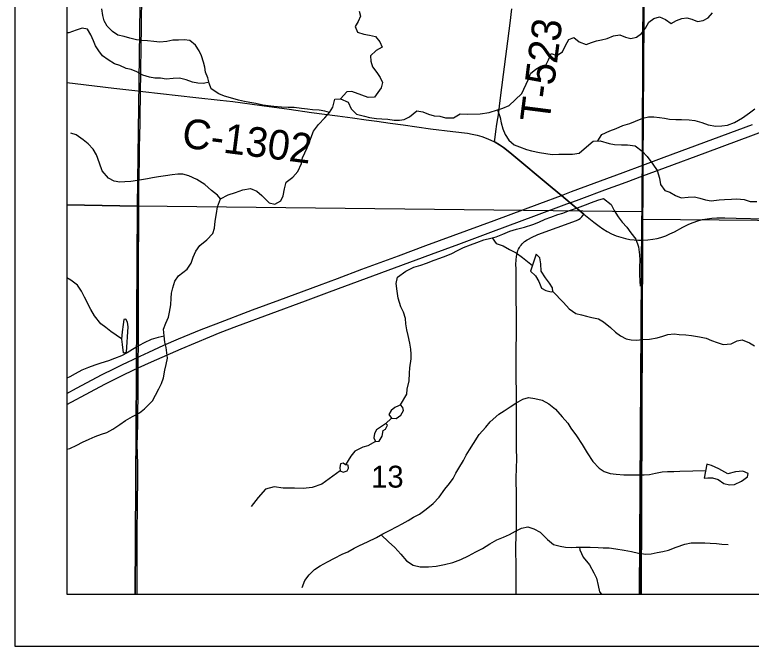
# Model space of a CAD drawing. Extents: x 0 to 34, y 0 to 22.
# Drawn here: x 2 to 3.412, y 14 to 15.21 of the extents above; entities that cross this region are included whole.
import ezdxf

# ---------------------------------------------------------------- set-up
doc = ezdxf.new("R2010")
doc.units = 0
for name, color, linetype in [('Default', 7, 'Continuous'), ('GM_X_County_Road', 7, 'Continuous'), ('GM_X_County_Road_Text', 7, 'Continuous'), ('GM_X_Interstate_Route', 7, 'Continuous'), ('GM_X_Minor_Lake', 7, 'Continuous'), ('GM_X_Minor_River', 7, 'Continuous'), ('GM_X_Section', 7, 'Continuous'), ('GM_X_Section_Text', 7, 'Continuous'), ('GM_X_Township_Road', 7, 'Continuous'), ('GM_X_Township_Road_Text', 7, 'Continuous'), ('SH_Cut_Line', 7, 'Continuous'), ('SH_Data', 7, 'Continuous')]:
    doc.layers.add(name, color=color, linetype=linetype)

msp = doc.modelspace()

# ---------------------------------------------------------------- linework, layer by layer
at = {"layer": 'Default'}
for points in [[(2.1, 15.8527), (2.1, 14.8453), (2.2353, 14.8433), (2.249, 15.8507)], [(2.1, 14.8453), (2.1, 14.1), (2.2309, 14.1), (2.2353, 14.8433)], [(2.2309, 14.1), (3.1977, 14.1), (3.2026, 14.8175), (3.2029, 14.8323), (2.2353, 14.8433)], [(3.1977, 14.1), (4.2188, 14.1), (4.2381, 14.8083), (3.2026, 14.8175)]]:
    msp.add_lwpolyline(points, close=True, dxfattribs=at)
at = {"layer": 'GM_X_County_Road'}
for points in [[(2.1, 15.0799), (2.1161, 15.078), (2.1901, 15.0692), (2.2301, 15.0646), (2.2411, 15.0635)], [(2.2411, 15.0635), (2.2456, 15.063), (2.2795, 15.059), (2.3474, 15.0514), (2.3936, 15.0463), (2.4183, 15.0433), (2.4737, 15.0357), (2.526, 15.0286), (2.5692, 15.0228), (2.6189, 15.0162), (2.6473, 15.0121), (2.6737, 15.0086), (2.694, 15.0057), (2.7198, 15.0023), (2.7446, 14.9986), (2.797, 14.9915), (2.8401, 14.9861), (2.8679, 14.9826), (2.8771, 14.981), (2.8863, 14.979), (2.8953, 14.9764), (2.9041, 14.9733), (2.9128, 14.9697), (2.9199, 14.9662)], [(2.9199, 14.9662), (2.9212, 14.9656), (2.9293, 14.9608), (2.937, 14.9554), (2.9492, 14.9457), (3.0305, 14.8784), (3.0481, 14.8637), (3.0567, 14.8565), (3.065, 14.8496), (3.0912, 14.8278)], [(3.0912, 14.8278), (3.1104, 14.8126), (3.1202, 14.8048), (3.1278, 14.7994), (3.1358, 14.7945), (3.1442, 14.7902), (3.1528, 14.7865), (3.1618, 14.7836), (3.1709, 14.7813), (3.1794, 14.7795), (3.1878, 14.7783), (3.1957, 14.7778), (3.204, 14.7777)], [(3.204, 14.7777), (3.2141, 14.7783), (3.2235, 14.7796), (3.2318, 14.7811), (3.2389, 14.7831), (3.2481, 14.7864), (3.2563, 14.79), (3.2648, 14.7941), (3.2812, 14.803), (3.2923, 14.8085), (3.3008, 14.812), (3.3096, 14.815), (3.3185, 14.8174), (3.3276, 14.8191), (3.3368, 14.8202), (3.346, 14.8207), (3.3615, 14.8209), (3.3832, 14.8203), (3.4391, 14.8187)]]:
    msp.add_lwpolyline(points, dxfattribs=at)
at = {"layer": 'GM_X_Interstate_Route'}
msp.add_lwpolyline([(2.1, 16.8784), (2.1, 14.1), (3.2011, 14.1), (3.2037, 14.7782), (3.2041, 14.9016), (3.2042, 14.9221), (3.2098, 15.7617), (3.2111, 16.7578), (3.2115, 16.8719), (3.0939, 16.8719), (2.6014, 16.878)], close=True, dxfattribs=at)
for points in [[(4.6269, 16.8701), (3.6554, 16.8713), (3.6203, 16.8714), (3.2115, 16.8719), (3.2111, 16.7578), (3.2098, 15.7617), (3.2042, 14.9221), (3.2041, 14.9016), (3.2037, 14.7782), (3.2011, 14.1), (8.2568, 14.1)], [(2.1, 14.4842), (2.1185, 14.4942), (2.1679, 14.5205), (2.19, 14.5317), (2.2067, 14.5399), (2.2368, 14.5539), (2.2405, 14.5556), (2.2574, 14.5636), (2.2856, 14.5765), (2.3141, 14.5888), (2.3572, 14.6065), (2.3861, 14.6179), (2.4558, 14.6444), (2.5083, 14.6637), (2.5374, 14.6744), (2.5841, 14.6916), (2.619, 14.7047), (2.6655, 14.7222), (2.7356, 14.7478), (2.788, 14.7675), (2.8404, 14.787), (2.9192, 14.8157), (3.0066, 14.8482), (3.0481, 14.8637), (3.0677, 14.871), (3.1668, 14.9076), (3.2044, 14.9216), (3.2454, 14.9368), (3.3387, 14.9711), (3.3853, 14.9885), (3.4144, 14.9993)], [(2.1, 14.4628), (2.145, 14.4876), (2.1725, 14.5022), (2.2059, 14.5189), (2.2284, 14.5297), (2.2367, 14.5334), (2.2624, 14.5451), (2.3194, 14.5698), (2.3738, 14.5929), (2.394, 14.6011), (2.426, 14.6133), (2.5573, 14.6615), (2.6038, 14.6789), (2.7992, 14.7512), (2.8516, 14.7705), (2.9127, 14.7935), (3.0002, 14.8256), (3.0585, 14.8472), (3.065, 14.8496), (3.0876, 14.858), (3.1314, 14.8741), (3.1722, 14.8892), (3.2043, 14.9011), (3.2479, 14.9173), (3.3237, 14.9455), (3.449, 14.9917)]]:
    msp.add_lwpolyline(points, dxfattribs=at)
at = {"layer": 'GM_X_Minor_Lake'}
for points in [[(2.9887, 14.7184), (2.9985, 14.7097), (3.0046, 14.6987), (3.01, 14.6858), (3.0183, 14.6813), (3.0282, 14.679), (3.0316, 14.6794), (3.0312, 14.6866), (3.0255, 14.6953), (3.0175, 14.7055), (3.0095, 14.7188), (3.0087, 14.7328), (3.0068, 14.7438), (2.9999, 14.7514)], [(2.9999, 14.7514), (2.9887, 14.7184)], [(2.7356, 14.4607), (2.7288, 14.4573), (2.722, 14.4515), (2.7175, 14.4439), (2.7221, 14.4367), (2.7315, 14.4364), (2.7402, 14.4429), (2.7451, 14.4516), (2.7444, 14.4573), (2.7396, 14.4627)], [(2.7396, 14.4627), (2.7356, 14.4607)], [(2.6937, 14.4143), (2.6899, 14.4078), (2.6888, 14.3991), (2.6918, 14.3923), (2.699, 14.393), (2.7043, 14.4025), (2.7062, 14.4132), (2.7107, 14.4158), (2.7145, 14.4234)], [(2.7145, 14.4234), (2.7129, 14.4257), (2.7108, 14.4263), (2.6937, 14.4143)], [(2.6343, 14.3477), (2.6298, 14.3507), (2.6244, 14.3492), (2.6233, 14.3423), (2.6241, 14.3363), (2.6298, 14.3333), (2.6374, 14.3359), (2.64, 14.3409), (2.6392, 14.3466)], [(2.6392, 14.3466), (2.6343, 14.3477)], [(3.3221, 14.3217), (3.3289, 14.3225), (3.3377, 14.3225), (3.3487, 14.3192), (3.3593, 14.3116), (3.3703, 14.309), (3.3802, 14.3101), (3.3934, 14.3163), (3.4048, 14.3243), (3.4063, 14.3311), (3.396, 14.3352), (3.382, 14.3341), (3.3669, 14.3302), (3.3501, 14.34), (3.3361, 14.3464), (3.327, 14.3487)], [(3.327, 14.3487), (3.3221, 14.3217)]]:
    msp.add_lwpolyline(points, dxfattribs=at)
at = {"layer": 'GM_X_Minor_River'}
for points in [[(2.3768, 15.0678), (2.3731, 15.0788), (2.3702, 15.0891), (2.3657, 15.0998), (2.3643, 15.1093), (2.3621, 15.1192), (2.358, 15.131), (2.3536, 15.1409), (2.3465, 15.1516), (2.336, 15.1604), (2.325, 15.1616), (2.314, 15.161), (2.303, 15.1611), (2.2916, 15.1585), (2.278, 15.1575), (2.2666, 15.1584), (2.2545, 15.16), (2.2436, 15.1602), (2.2333, 15.1618), (2.2209, 15.1649), (2.2095, 15.1681), (2.1978, 15.1705), (2.1873, 15.1778), (2.1772, 15.1877), (2.1716, 15.1984), (2.1686, 15.2083), (2.1668, 15.2208)], [(2.6602, 15.2168), (2.6631, 15.2069), (2.6585, 15.1971), (2.6527, 15.1873), (2.6572, 15.1762), (2.6693, 15.1727), (2.6802, 15.1707), (2.692, 15.1683), (2.6998, 15.1576), (2.7047, 15.1477), (2.6929, 15.1414), (2.6818, 15.1312), (2.6828, 15.1206), (2.6858, 15.1099), (2.6944, 15.0992), (2.7004, 15.0897), (2.7052, 15.0802), (2.7025, 15.0699)], [(2.9721, 15.059), (2.9843, 15.085), (2.9886, 15.0971), (2.9989, 15.1058), (3.0088, 15.111), (3.0183, 15.1132), (3.0236, 15.1233), (3.0287, 15.1354), (3.0392, 15.1319), (3.0499, 15.139), (3.0557, 15.1511), (3.0626, 15.1624), (3.0721, 15.1661), (3.0819, 15.1577), (3.0955, 15.153), (3.1057, 15.1563), (3.1152, 15.1596), (3.1251, 15.1614), (3.1357, 15.1644), (3.1479, 15.1696), (3.1604, 15.1713), (3.1709, 15.1667), (3.1811, 15.1643), (3.1918, 15.1665), (3.2017, 15.1736), (3.2093, 15.1842), (3.2159, 15.1955), (3.2254, 15.2026), (3.2364, 15.2055), (3.2477, 15.2009), (3.2586, 15.1928), (3.2689, 15.1988), (3.2788, 15.2028), (3.2886, 15.2039), (3.2984, 15.2011), (3.309, 15.1968), (3.3196, 15.199), (3.3295, 15.2039), (3.3379, 15.2136)], [(2.3727, 15.0803), (2.3621, 15.0778), (2.3508, 15.079), (2.3406, 15.0803), (2.3285, 15.085), (2.3157, 15.0881), (2.3035, 15.0875), (2.2906, 15.0865), (2.2797, 15.0881), (2.2683, 15.0882), (2.2585, 15.0902), (2.2453, 15.0941), (2.2343, 15.1003), (2.2234, 15.1046), (2.2136, 15.1069), (2.2015, 15.1127), (2.1913, 15.1159), (2.1789, 15.1236), (2.1683, 15.1313), (2.1612, 15.1408), (2.1549, 15.1504), (2.1508, 15.1599), (2.1456, 15.171), (2.1392, 15.182), (2.129, 15.184), (2.1176, 15.18), (2.1036, 15.1752), (2.1, 15.1751)], [(2.6035, 15.0226), (2.5948, 15.0252), (2.5834, 15.0271), (2.5709, 15.0274), (2.561, 15.0286), (2.5496, 15.03), (2.5359, 15.0319), (2.5242, 15.0322), (2.5113, 15.0326), (2.4965, 15.034), (2.4859, 15.0352), (2.4756, 15.0366), (2.462, 15.0396), (2.4509, 15.0419), (2.4407, 15.0434), (2.4289, 15.0464), (2.4134, 15.0505), (2.4024, 15.0539), (2.3913, 15.0584), (2.3768, 15.0678)], [(2.7025, 15.0699), (2.6899, 15.0518), (2.6774, 15.0513), (2.6656, 15.0558), (2.6466, 15.0626), (2.6368, 15.0618), (2.6247, 15.0485)], [(2.2762, 14.493), (2.2815, 14.5033), (2.2852, 14.5143), (2.2878, 14.5288), (2.2904, 14.5398), (2.2927, 14.5519), (2.2919, 14.5622), (2.2904, 14.572), (2.288, 14.5826), (2.2865, 14.5944), (2.2853, 14.6073), (2.2898, 14.6187), (2.2947, 14.6305), (2.297, 14.64), (2.2992, 14.654), (2.2999, 14.6665), (2.3007, 14.6764), (2.3029, 14.6866), (2.307, 14.6992), (2.3142, 14.7094), (2.3309, 14.7224), (2.3384, 14.7338), (2.3422, 14.7456), (2.3475, 14.757), (2.3546, 14.7676), (2.3686, 14.7787), (2.3796, 14.7905), (2.383, 14.8011), (2.3841, 14.814), (2.3867, 14.8292), (2.3886, 14.8417), (2.3946, 14.8569), (2.409, 14.8645), (2.4234, 14.8691), (2.4374, 14.8741), (2.4522, 14.8768), (2.4643, 14.8719), (2.4738, 14.8636), (2.4879, 14.8496), (2.4986, 14.847), (2.5099, 14.8531), (2.5144, 14.863), (2.5174, 14.8763), (2.5201, 14.8892), (2.5333, 14.8987), (2.5428, 14.9094), (2.5495, 14.9246), (2.5518, 14.9356), (2.5563, 14.9454), (2.5604, 14.9549), (2.5657, 14.9682), (2.5729, 14.9869), (2.5823, 14.9998), (2.5948, 15.0123), (2.6035, 15.0226), (2.6099, 15.0325), (2.614, 15.0481), (2.6247, 15.0485), (2.6391, 15.0421), (2.6448, 15.0296), (2.6555, 15.019), (2.6703, 15.0156), (2.6805, 15.0126), (2.6938, 15.0107), (2.7041, 15.0104), (2.7154, 15.0097), (2.7276, 15.0078), (2.7374, 15.0078), (2.7469, 15.009), (2.7568, 15.0144), (2.7708, 15.0254), (2.7825, 15.0235), (2.7935, 15.019), (2.8042, 15.0164), (2.8148, 15.0153), (2.8262, 15.0123), (2.841, 15.0123), (2.8539, 15.02), (2.8679, 15.0196), (2.8926, 15.0197), (2.9096, 15.0228), (2.9255, 15.0274), (2.9358, 15.0308), (2.9479, 15.0362), (2.9596, 15.0465), (2.9721, 15.059)], [(2.9259, 15.0275), (2.9309, 15.0126), (2.9328, 15.0024), (2.9359, 14.991), (2.9405, 14.9804), (2.9473, 14.9698), (2.9576, 14.9607), (2.9675, 14.9566), (2.9811, 14.9517), (2.991, 14.9491), (3.0062, 14.9461), (3.0183, 14.9438), (3.0305, 14.942), (3.043, 14.9424), (3.057, 14.9424), (3.0692, 14.9428), (3.0824, 14.9444), (3.0964, 14.9566), (3.1093, 14.9676), (3.1222, 14.9684), (3.1397, 14.9632), (3.1499, 14.9609), (3.1632, 14.9606), (3.1746, 14.9606), (3.1894, 14.9584), (3.2027, 14.9482), (3.2126, 14.938), (3.2232, 14.9236), (3.232, 14.9115), (3.2362, 14.8967), (3.2381, 14.8846), (3.2465, 14.8732), (3.256, 14.8698), (3.267, 14.8638), (3.2777, 14.8593), (3.2909, 14.8604), (3.3031, 14.8612), (3.3137, 14.8586), (3.3247, 14.8552), (3.3353, 14.8534), (3.3505, 14.8549), (3.3608, 14.8557), (3.374, 14.8565), (3.3846, 14.8569), (3.3983, 14.8558), (3.4101, 14.8517), (3.4226, 14.8521)], [(3.118, 14.9682), (3.1256, 14.9802), (3.1407, 14.9871), (3.1532, 14.9921), (3.1661, 14.9974), (3.179, 15.0012), (3.1904, 15.0058), (3.204, 15.0119), (3.215, 15.0139), (3.2256, 15.0143), (3.2359, 15.0132), (3.2461, 15.0117), (3.2556, 15.0094), (3.2674, 15.0091), (3.2784, 15.0091), (3.2928, 15.0084), (3.3042, 15.0069), (3.3171, 15.0032), (3.3296, 14.999), (3.3444, 14.9964), (3.3558, 14.9968), (3.3668, 14.9984), (3.38, 15.0034), (3.3952, 15.0121), (3.4088, 15.0221), (3.419, 15.0293)], [(2.3946, 14.8569), (2.3885, 14.8641), (2.3771, 14.8728), (2.3642, 14.8845), (2.3493, 14.8943), (2.3338, 14.9011), (2.3224, 14.9045), (2.3129, 14.9045), (2.3019, 14.9029), (2.289, 14.9014), (2.2757, 14.899), (2.264, 14.8971), (2.2545, 14.8956), (2.2355, 14.8921), (2.2227, 14.8905), (2.2113, 14.8894), (2.2018, 14.889), (2.1908, 14.8908), (2.1798, 14.8969), (2.1676, 14.9105), (2.1626, 14.9253), (2.1565, 14.9416), (2.1504, 14.9522), (2.1409, 14.9624), (2.131, 14.9703), (2.1177, 14.9794), (2.1078, 14.9828)], [(2.7396, 14.4627), (2.7515, 14.4831), (2.7526, 14.4926), (2.7564, 14.5086), (2.7571, 14.5234), (2.7578, 14.5336), (2.76, 14.5503), (2.76, 14.5598), (2.7592, 14.5693), (2.7573, 14.5807), (2.7542, 14.5955), (2.7519, 14.6061), (2.7496, 14.6174), (2.7492, 14.6277), (2.7454, 14.6402), (2.74, 14.6504), (2.7354, 14.6667), (2.7335, 14.6804), (2.7315, 14.6948), (2.7338, 14.7073), (2.7501, 14.7188), (2.7652, 14.726), (2.7785, 14.7302), (2.7895, 14.7341), (2.8042, 14.7398), (2.8148, 14.7432), (2.8273, 14.7482), (2.838, 14.7524), (2.8489, 14.7581), (2.8607, 14.7639), (2.8739, 14.7692), (2.8857, 14.7734), (2.8997, 14.7784), (2.9126, 14.7815), (2.9228, 14.7845), (2.9357, 14.7895), (2.9494, 14.7949), (2.9619, 14.7987), (2.9774, 14.8026), (2.9933, 14.8079), (3.0051, 14.8125), (3.0172, 14.8179), (3.0278, 14.8217), (3.0414, 14.827), (3.0509, 14.8297), (3.0638, 14.8347), (3.079, 14.84), (3.0945, 14.8454), (3.1059, 14.85), (3.118, 14.8546), (3.129, 14.8577), (3.1434, 14.8463), (3.1495, 14.8346), (3.1571, 14.8228), (3.1648, 14.8126), (3.1735, 14.8028), (3.1815, 14.7918), (3.191, 14.7797), (3.196, 14.7649), (3.1976, 14.7497), (3.1984, 14.7399), (3.198, 14.7266), (3.1981, 14.7122), (3.1985, 14.6993), (3.1989, 14.6898)], [(2.9153, 14.7823), (2.9232, 14.7717), (2.9365, 14.7671), (2.9487, 14.76), (2.9616, 14.7536), (2.9734, 14.7449), (2.9925, 14.7295)], [(2.205, 14.5888), (2.1844, 14.6032), (2.1749, 14.6104), (2.1654, 14.6179), (2.1529, 14.6331), (2.1456, 14.6452), (2.1338, 14.6687), (2.1277, 14.6804), (2.1201, 14.6918), (2.1075, 14.7016), (2.1, 14.7056)], [(3.0316, 14.6796), (3.0522, 14.6586), (3.0632, 14.6461), (3.0761, 14.6374), (3.0864, 14.6348), (3.0963, 14.6322), (3.1065, 14.6295), (3.119, 14.6269), (3.1289, 14.6216), (3.1422, 14.6103), (3.1517, 14.6016), (3.1612, 14.5944), (3.1726, 14.5891), (3.1821, 14.5869), (3.1916, 14.5866), (3.2041, 14.5873), (3.217, 14.5885), (3.2318, 14.5908), (3.2428, 14.5943), (3.2523, 14.597), (3.264, 14.5982), (3.2739, 14.597), (3.2864, 14.5967), (3.2974, 14.5956), (3.313, 14.593), (3.3259, 14.59), (3.3361, 14.5855), (3.3468, 14.5817), (3.3585, 14.578), (3.3733, 14.5791), (3.3851, 14.5849), (3.3949, 14.5872), (3.4086, 14.5815), (3.4181, 14.5755)], [(2.2081, 14.5619), (2.2141, 14.5634), (2.2174, 14.612), (2.2162, 14.6211), (2.2132, 14.6268), (2.209, 14.626), (2.2079, 14.6165), (2.2057, 14.6025), (2.205, 14.5884), (2.2057, 14.5778)], [(2.2866, 14.5938), (2.2751, 14.5917), (2.2619, 14.5875), (2.2482, 14.5814), (2.2384, 14.5764), (2.2255, 14.5684), (2.2157, 14.5623), (2.205, 14.5566), (2.1914, 14.5512), (2.18, 14.547), (2.1653, 14.542), (2.1535, 14.5382), (2.1414, 14.534), (2.1285, 14.5286), (2.1156, 14.5218), (2.1054, 14.5164), (2.1, 14.5133)], [(2.2057, 14.5778), (2.2081, 14.5619)], [(2.1, 14.3776), (2.1058, 14.3791), (2.1191, 14.3852), (2.1297, 14.3909), (2.1429, 14.3966), (2.1539, 14.402), (2.1664, 14.4062), (2.1767, 14.4093), (2.1884, 14.4158), (2.2016, 14.4245), (2.2126, 14.4325), (2.2259, 14.4402), (2.2391, 14.4474), (2.249, 14.455), (2.2641, 14.4702), (2.2701, 14.4809), (2.2762, 14.493)], [(2.5508, 14.1122), (2.5564, 14.1259), (2.5648, 14.1369), (2.575, 14.1472), (2.5859, 14.154), (2.5996, 14.1617), (2.6128, 14.1689), (2.6276, 14.1762), (2.6386, 14.1811), (2.6507, 14.188), (2.6613, 14.193), (2.6761, 14.2002), (2.6939, 14.2086), (2.706, 14.2155), (2.7185, 14.2216), (2.7333, 14.2296), (2.7431, 14.2346), (2.7545, 14.2407), (2.7643, 14.2472), (2.7761, 14.2529), (2.7886, 14.2624), (2.8022, 14.2735), (2.8139, 14.2856), (2.8249, 14.3012), (2.8336, 14.3119), (2.8404, 14.3214), (2.8456, 14.3313), (2.8513, 14.3411), (2.8607, 14.3556), (2.8656, 14.3659), (2.8717, 14.3765), (2.8796, 14.3887), (2.8906, 14.4058), (2.903, 14.4195), (2.9117, 14.4297), (2.928, 14.4446), (2.9386, 14.4507), (2.95, 14.4587), (2.9609, 14.4656), (2.9742, 14.4732), (2.9852, 14.4766), (2.9973, 14.4748), (3.0114, 14.4714), (3.0243, 14.4642), (3.0365, 14.454), (3.0498, 14.4397), (3.0604, 14.4275), (3.0665, 14.4177), (3.0768, 14.4029), (3.0879, 14.3863), (3.0974, 14.3704), (3.1085, 14.3541), (3.1203, 14.3412), (3.1298, 14.3348), (3.1415, 14.331), (3.1529, 14.3296), (3.1681, 14.3285), (3.1821, 14.3285), (3.1958, 14.3282), (3.2068, 14.3286), (3.217, 14.329), (3.2288, 14.3313), (3.2413, 14.3344), (3.2515, 14.3348), (3.2637, 14.3348), (3.2754, 14.3352), (3.3248, 14.3369)], [(2.7221, 14.4367), (2.7108, 14.4263)], [(2.6918, 14.3923), (2.6771, 14.3839), (2.6676, 14.3816), (2.6521, 14.3739), (2.6441, 14.3644), (2.6343, 14.3477)], [(2.6241, 14.3363), (2.5885, 14.3107), (2.57, 14.3039), (2.5529, 14.3023), (2.5362, 14.303), (2.5146, 14.3029), (2.4975, 14.3052), (2.4808, 14.3009), (2.4668, 14.2849), (2.4532, 14.2678)], [(2.7026, 14.2135), (2.7167, 14.2003), (2.7285, 14.1894), (2.7403, 14.1761), (2.7509, 14.1633), (2.7642, 14.155), (2.7775, 14.1523), (2.7931, 14.152), (2.8082, 14.1536), (2.8242, 14.1563), (2.8397, 14.1605), (2.8556, 14.1662), (2.87, 14.1731), (2.884, 14.1811), (2.8969, 14.1872), (2.9109, 14.1964), (2.9242, 14.2036), (2.937, 14.209), (2.9488, 14.214), (2.9598, 14.2204), (2.9719, 14.2265), (2.984, 14.2285), (2.9954, 14.2247), (3.0076, 14.2183), (3.0217, 14.2047), (3.0331, 14.1952), (3.0456, 14.1915), (3.0558, 14.19), (3.0668, 14.1893), (3.0763, 14.1897), (3.0904, 14.1897), (3.1033, 14.1898), (3.1184, 14.1894), (3.1279, 14.1887), (3.1397, 14.1884), (3.1522, 14.1869), (3.1685, 14.1839), (3.1822, 14.1813), (3.1962, 14.1783), (3.2099, 14.1764), (3.2205, 14.1772), (3.2319, 14.1795), (3.2425, 14.1815), (3.2535, 14.1842), (3.2683, 14.1895), (3.2849, 14.1953), (3.2967, 14.198), (3.31, 14.1984), (3.3232, 14.198), (3.3331, 14.1977), (3.3452, 14.1966), (3.3555, 14.1955), (3.368, 14.1948)], [(3.0828, 14.1897), (3.0835, 14.1848), (3.0897, 14.1708), (3.1018, 14.156), (3.1106, 14.1408), (3.1152, 14.1302), (3.1183, 14.1162), (3.121, 14.1041), (3.1249, 14.1)]]:
    msp.add_lwpolyline(points, dxfattribs=at)
at = {"layer": 'GM_X_Section'}
for points in [[(3.2082, 15.8593), (4.2651, 15.8107), (4.2381, 14.8083), (3.2026, 14.8175), (3.2029, 14.8323), (3.2075, 15.8525)], [(3.2075, 15.8525), (3.2029, 14.8323), (2.2353, 14.8433), (2.249, 15.8507)]]:
    msp.add_lwpolyline(points, close=True, dxfattribs=at)
at = {"layer": 'GM_X_Township_Road'}
for points in [[(2.2411, 15.0635), (2.2411, 15.068), (2.2415, 15.0912), (2.2417, 15.1005), (2.242, 15.1098), (2.2424, 15.1408), (2.2426, 15.1594), (2.2429, 15.1748), (2.2429, 15.1908), (2.243, 15.2047), (2.2434, 15.2336)], [(2.9262, 15.0111), (2.9272, 15.018), (2.9307, 15.0457), (2.9372, 15.095), (2.9497, 15.1935), (2.953, 15.2213)], [(2.237, 14.7198), (2.237, 14.7288), (2.2371, 14.7599), (2.2379, 14.7882), (2.2381, 14.8214), (2.238, 14.8375), (2.2381, 14.8685), (2.2382, 14.8809), (2.2386, 14.9057), (2.2391, 14.9274), (2.2395, 14.9553), (2.2403, 15.0019), (2.2407, 15.0268), (2.2409, 15.0454), (2.2411, 15.0635)], [(2.9199, 14.9662), (2.9213, 14.975), (2.9227, 14.986), (2.9246, 15.0003), (2.9262, 15.0111)], [(3.0912, 14.8278), (3.065, 14.8496), (3.0567, 14.8565), (3.0481, 14.8637), (3.0305, 14.8784), (2.9492, 14.9457), (2.937, 14.9554), (2.9293, 14.9608), (2.9212, 14.9656), (2.9199, 14.9662)], [(2.9611, 14.7227), (2.961, 14.731), (2.9612, 14.7403), (2.9618, 14.7464), (2.963, 14.7524), (2.9649, 14.7582), (2.9661, 14.7609), (2.9675, 14.7636), (2.9691, 14.7662), (2.9709, 14.7686), (2.9729, 14.7709), (2.975, 14.7731), (2.9773, 14.7751), (2.9823, 14.7786), (2.9849, 14.7801), (2.9905, 14.7829), (3.0028, 14.7885), (3.0397, 14.802), (3.0768, 14.8157), (3.0807, 14.8172), (3.084, 14.8196), (3.0871, 14.8226), (3.0912, 14.8278)], [(2.235, 14.3877), (2.2353, 14.4024), (2.2363, 14.4274), (2.2361, 14.4489), (2.2366, 14.4775), (2.2368, 14.5082), (2.2367, 14.5334), (2.2367, 14.5392), (2.2368, 14.5539), (2.237, 14.5703), (2.2371, 14.5983), (2.237, 14.6325), (2.2371, 14.6667), (2.2371, 14.7009), (2.237, 14.7198)], [(2.9613, 14.1), (2.9612, 14.1075), (2.9614, 14.1445), (2.9612, 14.1607), (2.9609, 14.1784), (2.9608, 14.1932), (2.9614, 14.2087), (2.9618, 14.2273), (2.9618, 14.2414), (2.962, 14.2585), (2.962, 14.274), (2.962, 14.2771), (2.962, 14.2802), (2.9618, 14.2989), (2.9617, 14.3113), (2.9617, 14.3237), (2.9621, 14.3392), (2.9625, 14.361), (2.9623, 14.3766), (2.9621, 14.3921), (2.9622, 14.4076), (2.962, 14.4263), (2.9619, 14.4387), (2.962, 14.4542), (2.9619, 14.476), (2.9618, 14.4884), (2.9613, 14.5125), (2.9612, 14.5308), (2.9616, 14.5568), (2.9618, 14.6097), (2.9618, 14.6346), (2.9615, 14.6688), (2.9614, 14.6906), (2.9612, 14.7123), (2.9611, 14.7227)], [(2.2346, 14.1), (2.2348, 14.1201), (2.2349, 14.1387), (2.235, 14.1511), (2.235, 14.1729), (2.2349, 14.204), (2.2356, 14.2817), (2.2358, 14.3128), (2.2358, 14.3376), (2.2358, 14.35), (2.2354, 14.367), (2.235, 14.3877)]]:
    msp.add_lwpolyline(points, dxfattribs=at)
at = {"layer": 'SH_Cut_Line'}
msp.add_lwpolyline([(2.1, 20.9), (2.1, 14.1), (8.2568, 14.1)], dxfattribs=at)
at = {"layer": 'SH_Data'}
for p, q in [((2, 21), (2, 14)), ((2.1, 20.9), (2.1, 14.1)), ((2.1, 14.1), (8.9, 14.1)), ((2.1, 14.1), (2.1, 14.1)), ((2, 14), (9, 14))]:
    msp.add_line(p, q, dxfattribs=at)

# ---------------------------------------------------------------- texts
at = {"layer": 'GM_X_County_Road_Text'}
msp.add_text('C-1302', height=0.05682, rotation=352.7357, dxfattribs=at).set_placement((2.3187, 14.9559))
at = {"layer": 'GM_X_Section_Text'}
msp.add_text('13', height=0.04186, rotation=0, dxfattribs=at).set_placement((2.6833, 14.3039))
at = {"layer": 'GM_X_Township_Road_Text'}
msp.add_text('T-523', height=0.05682, rotation=82.7008, dxfattribs=at).set_placement((3.025, 15.0017))

doc.saveas('drawing.dxf')
